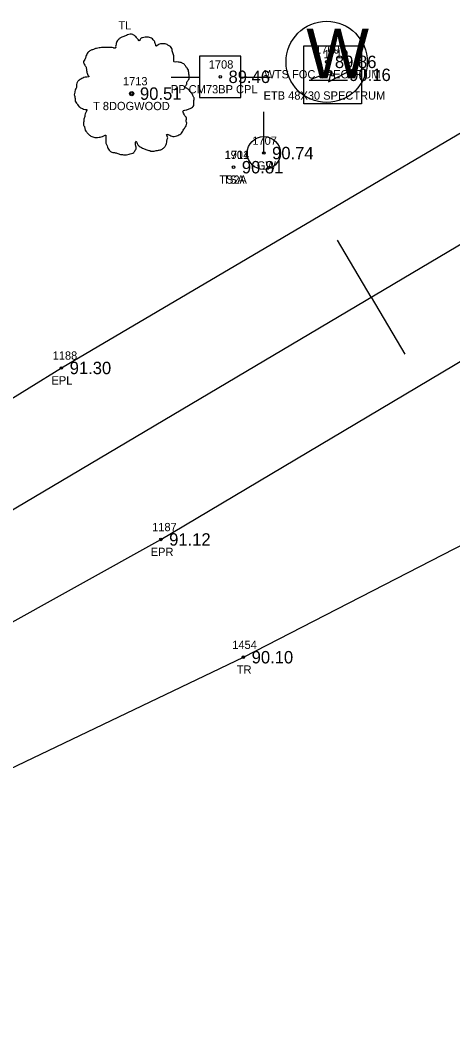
# Model space of a CAD drawing. Extents: x 2529517 to 2532038, y 935000 to 936944.
# Drawn here: x 2531203.8 to 2531256.1, y 935944.7 to 936067 of the extents above; entities that cross this region are included whole.
import ezdxf

# ---------------------------------------------------------------- set-up
doc = ezdxf.new("R2010")
doc.units = 0
for name, color, linetype in [('Default', 7, 'Continuous'), ('RD_DTM_BkLn_txCode', 7, 'Continuous'), ('RD_EX_Road', 7, 'Continuous'), ('RD_EX_Road_txCode', 7, 'Continuous'), ('RD_EX_TX_Misc_ELEV', 7, 'Continuous'), ('RD_EX_TX_Road_ELEV', 7, 'Continuous'), ('RD_EX_TX_UT_ELEV', 7, 'Continuous'), ('RD_EX_TX_VEG_ELEV', 7, 'Continuous'), ('RD_EX_UT', 7, 'Continuous'), ('RD_EX_UT_txCode', 7, 'Continuous'), ('RD_EX_VEG', 7, 'Continuous'), ('RD_EX_VEG_txCode', 7, 'Continuous'), ('RD_HC_Cl', 7, 'Continuous'), ('RD_HC_Data_Tic', 7, 'Continuous'), ('RD_HC_Survey_ELEV', 7, 'Continuous'), ('RD_SMD_Locator', 7, 'Continuous')]:
    doc.layers.add(name, color=color, linetype=linetype)

msp = doc.modelspace()

# ---------------------------------------------------------------- linework, layer by layer
at = {"layer": 'Default'}
msp.add_line((2530557.05, 935625.34), (2531768.07, 936342.55), dxfattribs=at)
at = {"layer": 'RD_EX_Road'}
for points in [[(2531169.65, 936000.77), (2531208.79, 936024.95), (2531292.04, 936074.02), (2531376.24, 936123.7), (2531460.37, 936174.49), (2531542.92, 936223.44), (2531626.67, 936270.85), (2531672.4, 936298.39), (2531714.28, 936327.21), (2531747.19, 936360.45), (2531761.42, 936377.32), (2531773.11, 936411.11), (2531782.2, 936441.65), (2531803.17, 936514.76), (2531820.28, 936585.8)], [(2531180.82, 935982), (2531220.82, 936004.21), (2531303.54, 936053.39), (2531388.75, 936103.71), (2531472.27, 936152.98), (2531554.79, 936201.9), (2531638.11, 936250.92), (2531683.19, 936278.28), (2531730.37, 936304.55), (2531771.5, 936341.26), (2531788.67, 936375.53), (2531805.57, 936434.84), (2531825.53, 936508.74), (2531844.13, 936579.65)]]:
    msp.add_lwpolyline(points, dxfattribs=at)
at = {"layer": 'RD_EX_UT'}
for p, q in [((2531230.49, 936062.67), (2531225.49, 936062.67)), ((2531225.49, 936062.67), (2531225.49, 936057.67)), ((2531230.49, 936057.67), (2531230.49, 936062.67)), ((2531222.06, 936060.1), (2531225.53, 936060.1)), ((2531230.42, 936060.1), (2531234.06, 936060.1)), ((2531238.74, 936059.76), (2531243.37, 936059.76)), ((2531225.49, 936057.67), (2531230.49, 936057.67)), ((2531233.27, 936050.94), (2531233.27, 936055.94))]:
    msp.add_line(p, q, dxfattribs=at)
msp.add_lwpolyline([(2531238.1, 936056.9), (2531238.1, 936063.9), (2531245.1, 936063.9), (2531245.1, 936056.9)], close=True, dxfattribs=at)
msp.add_lwpolyline([(2531239, 936059.89), (2531241.42, 936060.79), (2531241.08, 936059.55), (2531244.12, 936061.14)], dxfattribs=at)
for centre, radius in [((2531240.87, 936061.97), 4.91), ((2531233.27, 936050.94), 2)]:
    msp.add_circle(centre, radius, dxfattribs=at)
at = {"layer": 'RD_EX_VEG'}
msp.add_lwpolyline([(2531182.66, 935966.96), (2531230.8, 935989.97), (2531274.81, 936012.6), (2531313.69, 936036.35), (2531483.89, 936140.08), (2531501.35, 936141.05), (2531534.81, 936162.87), (2531566.74, 936177.64), (2531596.77, 936200.59), (2531599.53, 936176.46), (2531629.05, 936127.23), (2531618.55, 936099.22)], dxfattribs=at)
for centre, radius in [((2531217.29, 936058.13), 0.25), ((2531217.28, 936058.11), 0.0001)]:
    msp.add_circle(centre, radius, dxfattribs=at)
for points in [[(2531217.42, 936065.29), (2531217.12, 936065.32), (2531216.8, 936065.22), (2531216.55, 936065.12), (2531216.32, 936065.04), (2531216.1, 936064.94), (2531215.8, 936064.77), (2531215.57, 936064.57), (2531215.45, 936064.32), (2531215.4, 936064.1), (2531215.35, 936063.82), (2531215.35, 936063.65), (2531215.22, 936063.62), (2531215.07, 936063.65), (2531214.82, 936063.72), (2531214.57, 936063.72), (2531214.32, 936063.72), (2531213.97, 936063.7), (2531213.62, 936063.7), (2531213.35, 936063.65), (2531213.02, 936063.6), (2531212.65, 936063.47), (2531212.3, 936063.35), (2531212, 936063.1), (2531211.75, 936062.62), (2531211.62, 936062.27), (2531211.47, 936062.02), (2531211.62, 936061.57), (2531211.8, 936061.22), (2531211.82, 936061.02), (2531211.9, 936060.6), (2531212, 936060.37), (2531212.12, 936060.17), (2531212.05, 936060.15), (2531211.67, 936060.1), (2531211.37, 936060), (2531210.95, 936059.77), (2531210.72, 936059.55), (2531210.62, 936059.22), (2531210.6, 936058.87), (2531210.5, 936058.67), (2531210.42, 936058.4), (2531210.4, 936058.32), (2531210.35, 936058), (2531210.45, 936057.55), (2531210.47, 936057.2), (2531210.6, 936056.97), (2531210.75, 936056.8), (2531210.92, 936056.55), (2531211.32, 936056.32), (2531211.65, 936056.22), (2531211.85, 936056.2), (2531211.67, 936055.7), (2531211.62, 936055.35), (2531211.5, 936054.95), (2531211.5, 936054.87), (2531211.45, 936054.4), (2531211.6, 936054.07), (2531211.67, 936053.7), (2531211.85, 936053.47), (2531212.12, 936053.17), (2531212.45, 936052.95), (2531212.95, 936052.82), (2531213.35, 936052.85), (2531213.92, 936053.02), (2531214.17, 936053.1), (2531214.15, 936052.92), (2531214.17, 936052.55), (2531214.17, 936052.13), (2531214.32, 936051.8), (2531214.42, 936051.53), (2531214.57, 936051.28), (2531214.9, 936051.05), (2531215.3, 936050.98), (2531215.72, 936050.83), (2531216.17, 936050.75), (2531216.67, 936050.73), (2531217.27, 936050.88), (2531217.55, 936051), (2531217.65, 936051.18), (2531217.85, 936051.55), (2531217.8, 936051.78), (2531217.82, 936052.38), (2531217.92, 936052.2), (2531218.1, 936051.85), (2531218.6, 936051.55), (2531219, 936051.38), (2531219.47, 936051.23), (2531219.77, 936051.15), (2531220.24, 936051.23), (2531220.62, 936051.3), (2531220.99, 936051.43), (2531221.29, 936051.7), (2531221.47, 936051.98), (2531221.52, 936052.25), (2531221.59, 936052.63), (2531221.64, 936052.8)], [(2531221.64, 936052.8), (2531221.57, 936052.97), (2531221.52, 936053.22), (2531221.59, 936053.2), (2531221.77, 936053.15), (2531222.04, 936053.02), (2531222.27, 936052.95), (2531222.59, 936052.97), (2531222.87, 936053.07), (2531223.32, 936053.35), (2531223.59, 936053.82), (2531223.87, 936054.22), (2531223.94, 936054.55), (2531223.89, 936054.77), (2531223.87, 936055.27), (2531223.67, 936055.52), (2531223.62, 936055.65), (2531223.52, 936056.05), (2531223.59, 936056.1), (2531223.87, 936056.15), (2531224.24, 936056.27), (2531224.52, 936056.4), (2531224.74, 936056.57), (2531224.82, 936056.8), (2531224.79, 936057.2), (2531224.84, 936057.6), (2531224.77, 936057.75), (2531224.67, 936057.9), (2531224.59, 936058.1), (2531224.44, 936058.25), (2531224.34, 936058.4), (2531224.24, 936058.5), (2531224.12, 936058.65), (2531223.94, 936058.77), (2531223.79, 936058.82), (2531223.74, 936058.97), (2531223.89, 936059.17), (2531223.94, 936059.27), (2531223.97, 936059.5), (2531224.19, 936059.85), (2531224.24, 936060.25), (2531224.19, 936060.67), (2531224.14, 936060.95), (2531223.99, 936061.22), (2531223.79, 936061.47), (2531223.67, 936061.65), (2531223.49, 936061.77), (2531223.17, 936061.9), (2531222.92, 936061.95), (2531222.57, 936061.95), (2531222.37, 936062), (2531222.39, 936062.05), (2531222.39, 936062.2), (2531222.39, 936062.47), (2531222.32, 936062.92), (2531222.17, 936063.42), (2531222.17, 936063.45), (2531222.07, 936063.7), (2531221.84, 936063.9), (2531221.67, 936064), (2531221.47, 936064.12), (2531221.22, 936064.15), (2531220.92, 936064.15), (2531220.64, 936064.1), (2531220.44, 936064), (2531220.27, 936063.87), (2531220.19, 936064.02), (2531220.1, 936064.32), (2531220.05, 936064.47), (2531219.9, 936064.64), (2531219.67, 936064.84), (2531219.22, 936064.97), (2531218.6, 936064.89), (2531218.3, 936064.69), (2531218.15, 936064.52), (2531218.1, 936064.64), (2531217.9, 936064.84), (2531217.8, 936065.02), (2531217.62, 936065.14), (2531217.47, 936065.24), (2531217.37, 936065.29)]]:
    msp.add_spline(points, degree=3, dxfattribs=at)
at = {"layer": 'RD_HC_Cl'}
msp.add_line((2530557.05, 935625.34), (2531768.07, 936342.55), dxfattribs=at)
at = {"layer": 'RD_HC_Data_Tic'}
for q in [(2531242.16, 936040.39), (2531250.31, 936026.62)]:
    msp.add_line((2531246.24, 936033.51), q, dxfattribs=at)
at = {"layer": 'RD_SMD_Locator'}
for centre in [(2531240.87, 936061.97), (2531228, 936060.16), (2531241.6, 936060.4), (2531217.29, 936058.13), (2531233.27, 936050.94), (2531229.61, 936049.23), (2531229.61, 936049.23), (2531208.79, 936024.95), (2531220.82, 936004.21), (2531230.8, 935989.97)]:
    msp.add_circle(centre, 0.15, dxfattribs=at)

# ---------------------------------------------------------------- texts
at = {"layer": 'RD_DTM_BkLn_txCode'}
for s, p in [('1901', (2531228.51, 936050.23)), ('1714', (2531228.55, 936050.23)), ('TS2A', (2531227.88, 936047.23)), ('TSA', (2531228.33, 936047.23))]:
    msp.add_text(s, height=1, dxfattribs=at).set_placement(p)
at = {"layer": 'RD_EX_Road_txCode'}
for s, p in [('1188', (2531207.73, 936025.95)), ('EPL', (2531207.59, 936022.95)), ('1187', (2531219.76, 936005.21)), ('EPR', (2531219.59, 936002.21))]:
    msp.add_text(s, height=1, dxfattribs=at).set_placement(p)
at = {"layer": 'RD_EX_TX_Misc_ELEV'}
msp.add_text('90.81', height=1.5, dxfattribs=at).set_placement((2531230.61, 936048.48))
msp.add_text('90.81', height=1.5, dxfattribs=at).set_placement((2531230.61, 936048.48))
at = {"layer": 'RD_EX_TX_Road_ELEV'}
for s, p in [('91.30', (2531209.79, 936024.2)), ('91.12', (2531221.82, 936003.46))]:
    msp.add_text(s, height=1.5, dxfattribs=at).set_placement(p)
at = {"layer": 'RD_EX_TX_UT_ELEV'}
for s, p in [('89.86', (2531241.87, 936061.22)), ('90.16', (2531243.6, 936059.65)), ('90.74', (2531234.27, 936050.19))]:
    msp.add_text(s, height=1.5, dxfattribs=at).set_placement(p)
at = {"layer": 'RD_EX_TX_VEG_ELEV'}
for s, p in [('90.51', (2531218.29, 936057.38)), ('90.10', (2531231.8, 935989.22))]:
    msp.add_text(s, height=1.5, dxfattribs=at).set_placement(p)
at = {"layer": 'RD_EX_UT'}
msp.add_text('W', height=6, dxfattribs=at).set_placement((2531238.41, 936059.97))
at = {"layer": 'RD_EX_UT_txCode'}
for s, p in [('1709', (2531239.48, 936062.97)), ('1710', (2531240.5, 936062.4)), ('1708', (2531226.61, 936061.16)), ('WTS FOC SPECTRUM', (2531233.34, 936059.97)), ('PP CM73BP CPL', (2531222.03, 936058.16)), ('ETB 48X30 SPECTRUM', (2531233.24, 936057.4)), ('1707', (2531231.88, 936051.94)), ('GW', (2531232.43, 936048.94))]:
    msp.add_text(s, height=1, dxfattribs=at).set_placement(p)
at = {"layer": 'RD_EX_VEG_txCode'}
for s, p in [('TL', (2531215.68, 936065.89)), ('1713', (2531216.23, 936059.13)), ('T 8DOGWOOD', (2531212.61, 936056.13)), ('1454', (2531229.45, 935990.97)), ('TR', (2531230, 935987.97))]:
    msp.add_text(s, height=1, dxfattribs=at).set_placement(p)
at = {"layer": 'RD_HC_Survey_ELEV'}
msp.add_text('89.46', height=1.5, dxfattribs=at).set_placement((2531229, 936059.41))

doc.saveas('drawing.dxf')
